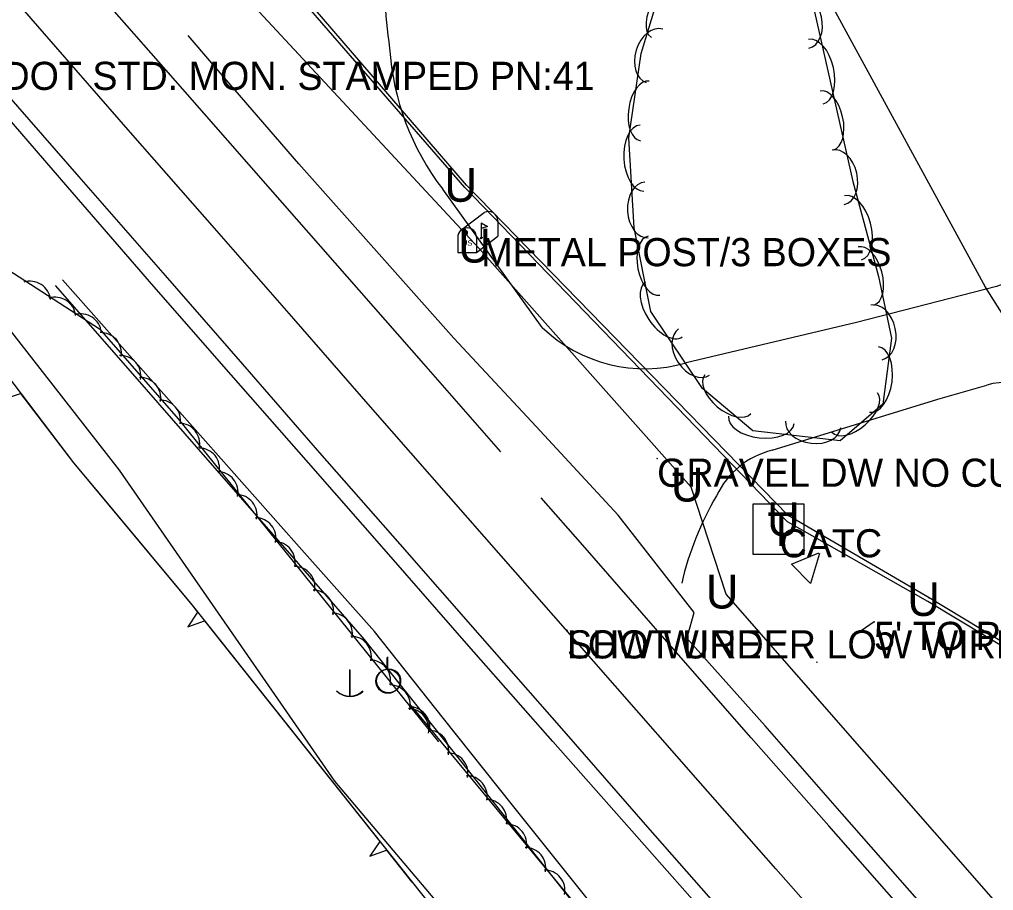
# Model space of a CAD drawing. Extents: x 954793 to 988390, y 1867850 to 1924428.
# Drawn here: x 966179.6 to 966352.5, y 1897839.5 to 1897994.2 of the extents above; entities that cross this region are included whole.
import ezdxf

# ---------------------------------------------------------------- set-up
doc = ezdxf.new("R2010")
doc.units = 0
for name, color, linetype in [('Default', 7, 'Continuous'), ('S_DITCHLINE', 7, 'Continuous'), ('S_DRIVEWAY', 7, 'Continuous'), ('S_EDGE_PAVEMENT', 7, 'Continuous'), ('S_ELECTRIC_UTILITIES_ANNOT', 7, 'Continuous'), ('S_FENCE', 7, 'Continuous'), ('S_FIBER_OPTIC_CABLE', 7, 'Continuous'), ('S_GRD_PT_SYM', 7, 'Continuous'), ('S_MAILBOX', 7, 'Continuous'), ('S_MAILBOX_ANNOT', 7, 'Continuous'), ('S_MISC_TOPO_POINT', 7, 'Continuous'), ('S_MSC_PT_SYM', 7, 'Continuous'), ('S_PAVEMENT_CROWN', 7, 'Continuous'), ('S_PRIMARY_CTL_ANNOT', 7, 'Continuous'), ('S_SHOULDER', 7, 'Continuous'), ('S_SIGN', 7, 'Continuous'), ('S_SIGN_ANNOT', 7, 'Continuous'), ('S_SURVEY_TEXT_ANNOT', 7, 'Continuous'), ('S_TELEPHONE_UTILITIES', 7, 'Continuous'), ('S_TELEPHONE_UTILITIES_ANNOT', 7, 'Continuous'), ('S_TREE', 7, 'Continuous'), ('S_UNDERGROUND_CABLE', 7, 'Continuous'), ('S_UTILITY_POLE', 7, 'Continuous'), ('S_UTL_PT_SYM', 7, 'Continuous'), ('S_WATER_UTILITIES', 7, 'Continuous')]:
    doc.layers.add(name, color=color, linetype=linetype)

msp = doc.modelspace()

# ---------------------------------------------------------------- linework, layer by layer
at = {"layer": 'S_DITCHLINE'}
for points in [[(966277.77, 1897837.5), (966265.47, 1897853.02), (966253.17, 1897868.55), (966240.87, 1897884.08), (966227.16, 1897899.8), (966213.45, 1897915.51), (966199.74, 1897931.23), (966186.02, 1897946.94)], [(966392.34, 1897728.07), (966388.47, 1897726.34), (966381.09, 1897729.16), (966372.46, 1897738.43), (966363.84, 1897747.69), (966355.22, 1897756.95), (966346.59, 1897766.21), (966332.87, 1897780.62), (966319.15, 1897795.02), (966305.43, 1897809.43), (966291.71, 1897823.83), (966279.44, 1897839.24), (966267.16, 1897854.64), (966254.89, 1897870.05), (966242.61, 1897885.46), (966228.77, 1897901.08), (966214.93, 1897916.71), (966201.08, 1897932.34), (966187.24, 1897947.96)]]:
    msp.add_lwpolyline(points, dxfattribs=at)
at = {"layer": 'S_DRIVEWAY'}
for points in [[(966298.25, 1897884.8), (966299.4, 1897888.84), (966285.91, 1897906.15), (966271.31, 1897921.87), (966256.71, 1897937.59), (966242.96, 1897953.06), (966229.22, 1897968.54), (966213.77, 1897986.42), (966209.53, 1897991.33)], [(966272.39, 1897939.5), (966254.75, 1897964.03)], [(966364.99, 1897951.02), (966353.07, 1897946.76), (966328.19, 1897940.39), (966297.97, 1897933.19), (966297.97, 1897933.19)], [(966313.22, 1897917.67), (966342.63, 1897926.74), (966351.33, 1897929.24)]]:
    msp.add_lwpolyline(points, dxfattribs=at)
for centre, major_axis, ratio, start_param, end_param in [((966324.49, 1898001.33), (7.1, -79.88), 0.998976, 4.323748, 4.776764), ((966291.37, 1897992.13), (10.81, -44.9), 0.999649, 4.541714, 5.130509), ((966290.68, 1897958.57), (17.96, 19.38), 0.99937, 3.124348, 4.168887), ((966354.85, 1897916.74), (-4.68, 12.12), 0.997266, 4.827112, 6.188789), ((966316.74, 1897903.37), (-13.94, 4.81), 0.997419, 5.284787, 6.178987), ((966349.7, 1897881.97), (-1.95, -54.11), 0.995184, 4.212702, 4.522521)]:
    msp.add_ellipse(centre, major_axis=major_axis, ratio=ratio, start_param=start_param, end_param=end_param, dxfattribs=at)
at = {"layer": 'S_EDGE_PAVEMENT'}
for points in [[(966265.05, 1897917.41), (966251.37, 1897933), (966237.77, 1897948.52), (966224.16, 1897964.05), (966208.61, 1897981.8), (966193.05, 1897999.56), (966178.87, 1898015.87), (966164.68, 1898032.17), (966151.2, 1898047.7), (966141.65, 1898058.71)], [(966305.02, 1897834.99), (966291.18, 1897850.72), (966276.29, 1897867.75), (966261.39, 1897884.77), (966247.17, 1897900.98), (966232.94, 1897917.2), (966219.25, 1897932.95), (966205.55, 1897948.71), (966190.18, 1897966.26), (966174.81, 1897983.8), (966160.53, 1898000.09), (966146.26, 1898016.39), (966132.83, 1898031.8), (966126.31, 1898039.28)], [(966556.69, 1897584.26), (966542.29, 1897600.66), (966526.72, 1897618.45), (966511.14, 1897636.23), (966496.26, 1897653.21), (966481.38, 1897670.18), (966466.51, 1897687.2), (966451.64, 1897704.23), (966438.16, 1897719.65), (966424.67, 1897735.06), (966409.56, 1897752.36), (966394.45, 1897769.66), (966380.51, 1897785.67), (966366.57, 1897801.68), (966351.81, 1897818.51), (966337.05, 1897835.34), (966323.28, 1897850.98), (966309.51, 1897866.62), (966294.55, 1897883.73), (966279.6, 1897900.83), (966272.22, 1897909.24)]]:
    msp.add_lwpolyline(points, dxfattribs=at)
at = {"layer": 'S_FENCE'}
msp.add_lwpolyline([(966321.61, 1897899.33), (966320.04, 1897893.99), (966316.69, 1897897.41), (966321.5, 1897899.48)], dxfattribs=at)
at = {"layer": 'S_FIBER_OPTIC_CABLE'}
for p, q in [((966258.99, 1897964.73), (966197.27, 1898036.41)), ((966316.08, 1897906.07), (966258.99, 1897964.73)), ((966197.33, 1897914.12), (966170.05, 1897949.09)), ((966235.58, 1897858.91), (966197.33, 1897914.12)), ((966341.1, 1897891.46), (966316.08, 1897906.07)), ((966389.25, 1897862.41), (966341.1, 1897891.46)), ((966273.18, 1897814.48), (966235.58, 1897858.91))]:
    msp.add_line(p, q, dxfattribs=at)
at = {"layer": 'S_GRD_PT_SYM'}
msp.add_lwpolyline([(966276.81, 1897885.69), (966276.81, 1897885.74), (966276.81, 1897885.69), (966276.76, 1897885.69), (966276.81, 1897885.69), (966276.81, 1897885.64), (966276.81, 1897885.69), (966276.86, 1897885.69)], dxfattribs=at)
at = {"layer": 'S_MAILBOX'}
for p, q in [((966257.96, 1897956.78), (966262.1, 1897959.89)), ((966261.58, 1897958.07), (966261.58, 1897955.36)), ((966264.53, 1897958.42), (966264.53, 1897955.7)), ((966260.73, 1897952.79), (966264.53, 1897955.7)), ((966257.41, 1897955.51), (966257.41, 1897952.79)), ((966260.73, 1897955.51), (966260.73, 1897952.79)), ((966257.41, 1897952.79), (966260.73, 1897952.79))]:
    msp.add_line(p, q, dxfattribs=at)
for points in [[(966261.58, 1897958.07), (966262.69, 1897957.41), (966261.58, 1897957.06)], [(966258.59, 1897956.62), (966258.82, 1897956.48), (966258.82, 1897956.1), (966259.12, 1897956.1), (966259.12, 1897956.46), (966258.93, 1897956.71), (966258.59, 1897956.65)]]:
    msp.add_lwpolyline(points, dxfattribs=at)
for centre, end in [((966262.87, 1897958.42), 117.5718), ((966259.07, 1897955.51), 180)]:
    msp.add_arc(centre, 1.66, 0, end, dxfattribs=at)
msp.add_ellipse((966261.58, 1897955.36), major_axis=(0.145, 0.132), ratio=0.564646, dxfattribs=at)
at = {"layer": 'S_MSC_PT_SYM'}
for points in [[(966292.81, 1897916.18), (966292.81, 1897916.23), (966292.81, 1897916.18), (966292.76, 1897916.18), (966292.81, 1897916.18), (966292.81, 1897916.13), (966292.81, 1897916.18), (966292.86, 1897916.18)], [(966331.33, 1897887.2), (966331.33, 1897887.25), (966331.33, 1897887.2), (966331.28, 1897887.2), (966331.33, 1897887.2), (966331.33, 1897887.15), (966331.33, 1897887.2), (966331.38, 1897887.2)], [(966321.19, 1897880.05), (966321.19, 1897880.1), (966321.19, 1897880.05), (966321.14, 1897880.05), (966321.19, 1897880.05), (966321.19, 1897880), (966321.19, 1897880.05), (966321.24, 1897880.05)]]:
    msp.add_lwpolyline(points, dxfattribs=at)
at = {"layer": 'S_PAVEMENT_CROWN'}
msp.add_lwpolyline([(966327.65, 1897827.67), (966313.88, 1897843.35), (966300.1, 1897859.03), (966285.36, 1897875.84), (966270.62, 1897892.65), (966256.27, 1897909.02), (966241.93, 1897925.38), (966228.28, 1897941.01), (966214.62, 1897956.65), (966199.33, 1897974.13), (966184.03, 1897991.61), (966169.77, 1898008.02)], dxfattribs=at)
at = {"layer": 'S_SHOULDER'}
for points in [[(966303.14, 1897833.34), (966289.22, 1897849.08), (966274.31, 1897865.97), (966259.39, 1897882.86), (966245.17, 1897899.15), (966230.94, 1897915.43), (966217.21, 1897931.09), (966203.47, 1897946.76), (966188.18, 1897964.39), (966172.89, 1897982.03), (966158.65, 1897998.25), (966144.41, 1898014.47), (966130.85, 1898029.95), (966122.89, 1898039.03)], [(966558.56, 1897586.04), (966544.15, 1897602.56), (966528.65, 1897620.34), (966513.15, 1897638.13), (966498.37, 1897655.11), (966483.59, 1897672.1), (966468.73, 1897689.17), (966453.87, 1897706.23), (966440.45, 1897721.69), (966427.03, 1897737.14), (966412.09, 1897754.39), (966397.14, 1897771.65), (966382.99, 1897787.71), (966368.83, 1897803.77), (966354.11, 1897820.62), (966339.38, 1897837.46), (966325.68, 1897853.09), (966311.99, 1897868.71), (966298.11, 1897884.29)]]:
    msp.add_lwpolyline(points, dxfattribs=at)
at = {"layer": 'S_SIGN'}
msp.add_line((966331.33, 1897887.2), (966328.26, 1897885.04), dxfattribs=at)
at = {"layer": 'S_TELEPHONE_UTILITIES'}
msp.add_lwpolyline([(966309.84, 1897899.14), (966309.84, 1897908.14), (966318.84, 1897908.14), (966318.84, 1897899.14)], close=True, dxfattribs=at)
at = {"layer": 'S_TREE'}
for p, q in [((966176.8, 1897926.77), (966179.81, 1897927.77)), ((966211.23, 1897888.89), (966209.47, 1897886.28)), ((966209.47, 1897886.28), (966212.45, 1897887.35)), ((966243.55, 1897848.19), (966241.79, 1897845.59)), ((966241.79, 1897845.59), (966244.77, 1897846.65))]:
    msp.add_line(p, q, dxfattribs=at)
for points in [[(966004.3, 1897880.13), (966059.66, 1897915.24), (966086.88, 1897921.09), (966104.68, 1897925.07), (966112.45, 1897935.52), (966106.92, 1897948.08), (966090.61, 1897968.77), (966074.51, 1897985.5), (966067.36, 1897991.4), (966058.74, 1898002.25), (966054.98, 1898014.16), (966059.62, 1898020.14), (966075.09, 1898023.53), (966101.4, 1898008.02), (966123.07, 1897993.04), (966147.23, 1897971.38), (966166.44, 1897945.33), (966189.19, 1897915.45), (966210.24, 1897890.13), (966252.56, 1897836.85)], [(966319.9, 1897999.25), (966327.57, 1897965.38), (966332.11, 1897948.56), (966334.43, 1897937.57), (966332.87, 1897925.87), (966325.28, 1897919.34), (966309.79, 1897921.12), (966300.85, 1897928.63), (966291.69, 1897942.34), (966288.74, 1897957.16), (966287.77, 1897973.15), (966289.98, 1897988.15), (966292.25, 1897995.52), (966294.55, 1897998.96), (966306.08, 1898004.97), (966313.11, 1898004.57), (966318.51, 1898000.87), (966320.58, 1897997.56)], [(966148.95, 1897968.26), (966193.8, 1897939.26), (966207.79, 1897923.25), (966253.99, 1897865.87)], [(966179.81, 1897927.77), (966189.19, 1897915.45), (966195.27, 1897908.13)], [(966195.27, 1897908.13), (966210.24, 1897890.13), (966211.23, 1897888.89)], [(966212.45, 1897887.35), (966228, 1897867.77)], [(966249.08, 1897872.34), (966354.07, 1897745.39), (966390.72, 1897702.43), (966457.35, 1897631.88), (966516.54, 1897569.35)], [(966228, 1897867.77), (966243.55, 1897848.19)], [(966244.77, 1897846.65), (966249.28, 1897840.97)]]:
    msp.add_lwpolyline(points, dxfattribs=at)
for centre, start, end in [((966181.48, 1897944.06), 6.3158, 107.9127), ((966185.95, 1897941.21), 6.3158, 107.9127), ((966190.52, 1897938.25), 6.3158, 107.9127), ((966194.06, 1897934.92), 350.3475, 91.9444), ((966197.51, 1897930.86), 350.3475, 91.9444), ((966201.05, 1897926.93), 350.3475, 91.9444), ((966204.56, 1897922.95), 350.3475, 91.9444), ((966207.96, 1897918.84), 348.0399, 89.6368), ((966211.48, 1897914.43), 348.0399, 89.6368), ((966214.77, 1897910.22), 348.0399, 89.6368), ((966218.14, 1897906.16), 348.0399, 89.6368), ((966221.49, 1897902.05), 348.0399, 89.6368), ((966224.9, 1897897.81), 348.0399, 89.6368), ((966228.42, 1897893.39), 348.0399, 89.6368), ((966231.71, 1897889.19), 348.0399, 89.6368), ((966235.08, 1897885.12), 348.0399, 89.6368), ((966238.43, 1897881.01), 348.0399, 89.6368), ((966241.84, 1897876.77), 348.0399, 89.6368), ((966245.36, 1897872.35), 348.0399, 89.6368), ((966248.64, 1897868.15), 348.0399, 89.6368), ((966248.83, 1897868.46), 348.7944, 90.3913), ((966252.17, 1897864.31), 348.7944, 90.3913), ((966255.59, 1897860.28), 348.7944, 90.3913), ((966259, 1897856.22), 348.7944, 90.3913), ((966262.47, 1897852.02), 348.7944, 90.3913), ((966266.04, 1897847.65), 348.7944, 90.3913), ((966269.39, 1897843.49), 348.7944, 90.3913), ((966272.81, 1897839.47), 348.7944, 90.3913)]:
    msp.add_arc(centre, 3.64, start, end, dxfattribs=at)
for centre, major_axis, ratio in [((966295.04, 1897995.87), (-3.26, -4.88), 0.55008), ((966318.67, 1897993.89), (-1.09, 4.83), 0.685311), ((966292.34, 1897987.73), (-1.46, -4.74), 0.685311), ((966320.97, 1897984.92), (-1.29, 5.72), 0.55008), ((966290.62, 1897977.94), (-0.78, -5.29), 0.540699), ((966322.93, 1897976.27), (-1.18, 5.21), 0.540699), ((966290.12, 1897969.57), (0.35, -5.86), 0.55008), ((966324.95, 1897966.16), (-1.09, 4.83), 0.685311), ((966290.94, 1897960.34), (0.3, -4.95), 0.685311), ((966327.58, 1897957.18), (-1.53, 5.67), 0.55008), ((966292.24, 1897950.45), (1.04, -5.24), 0.540699), ((966329.9, 1897948.62), (-1.39, 5.16), 0.540699), ((966294.02, 1897942.67), (3.26, -4.88), 0.55008), ((966331.77, 1897938.61), (-1.02, 4.85), 0.685311), ((966299.38, 1897935.12), (2.75, -4.12), 0.685311), ((966331.31, 1897930.23), (0.78, 5.82), 0.55008), ((966305.35, 1897927.62), (4.09, -3.44), 0.540699), ((966327.87, 1897924.38), (4.05, 3.49), 0.540699), ((966311.31, 1897923.08), (5.83, -0.67), 0.55008), ((966320.53, 1897922.28), (4.92, -0.57), 0.685311)]:
    msp.add_ellipse(centre, major_axis=major_axis, ratio=ratio, start_param=3.141593, end_param=6.283185, dxfattribs=at)
at = {"layer": 'S_UNDERGROUND_CABLE'}
for p, q in [((966261.13, 1897953.54), (966185.07, 1898035.55)), ((966258.67, 1897964.36), (966196.56, 1898036)), ((966315.95, 1897904.98), (966258.67, 1897964.36)), ((966298.88, 1897911.11), (966261.13, 1897953.54)), ((966305.08, 1897892.1), (966298.88, 1897911.11)), ((966340.86, 1897890.78), (966315.95, 1897904.98)), ((966362.5, 1897826.48), (966305.08, 1897892.1)), ((966388.86, 1897861.94), (966340.86, 1897890.78))]:
    msp.add_line(p, q, dxfattribs=at)
at = {"layer": 'S_UTILITY_POLE'}
for p, q in [((966244.9, 1897878.78), (966244.9, 1897880.88)), ((966245.02, 1897878.87), (966245.02, 1897880.98)), ((966238.17, 1897878.72), (966238.17, 1897874)), ((966238.23, 1897878.64), (966238.23, 1897873.91))]:
    msp.add_line(p, q, dxfattribs=at)
for centre in [(966245.02, 1897876.63), (966245.14, 1897876.73)]:
    msp.add_circle(centre, 2.13, dxfattribs=at)
for centre in [(966238.23, 1897877.42), (966238.29, 1897877.34)]:
    msp.add_arc(centre, 3.41, 226.3972, 313.6028, dxfattribs=at)
at = {"layer": 'S_UTL_PT_SYM'}
for points in [[(966258.99, 1897964.73), (966258.99, 1897964.78), (966258.99, 1897964.73), (966258.94, 1897964.73), (966258.99, 1897964.73), (966258.99, 1897964.68), (966258.99, 1897964.73), (966259.04, 1897964.73)], [(966351.09, 1897946.65), (966351.09, 1897946.7), (966351.09, 1897946.65), (966351.04, 1897946.65), (966351.09, 1897946.65), (966351.09, 1897946.6), (966351.09, 1897946.65), (966351.14, 1897946.65)], [(966197.33, 1897914.12), (966197.33, 1897914.17), (966197.33, 1897914.12), (966197.28, 1897914.12), (966197.33, 1897914.12), (966197.33, 1897914.07), (966197.33, 1897914.12), (966197.38, 1897914.12)], [(966316.08, 1897906.07), (966316.08, 1897906.12), (966316.08, 1897906.07), (966316.03, 1897906.07), (966316.08, 1897906.07), (966316.08, 1897906.02), (966316.08, 1897906.07), (966316.13, 1897906.07)], [(966341.1, 1897891.46), (966341.1, 1897891.51), (966341.1, 1897891.46), (966341.05, 1897891.46), (966341.1, 1897891.46), (966341.1, 1897891.41), (966341.1, 1897891.46), (966341.15, 1897891.46)], [(966276.81, 1897885.69), (966276.81, 1897885.74), (966276.81, 1897885.69), (966276.76, 1897885.69), (966276.81, 1897885.69), (966276.81, 1897885.64), (966276.81, 1897885.69), (966276.86, 1897885.69)], [(966235.58, 1897858.91), (966235.58, 1897858.96), (966235.58, 1897858.91), (966235.53, 1897858.91), (966235.58, 1897858.91), (966235.58, 1897858.86), (966235.58, 1897858.91), (966235.63, 1897858.91)]]:
    msp.add_lwpolyline(points, dxfattribs=at)
at = {"layer": 'S_WATER_UTILITIES'}
for p, q in [((966351.09, 1897946.65), (966312.55, 1898017.63)), ((966368.94, 1897918.36), (966351.09, 1897946.65))]:
    msp.add_line(p, q, dxfattribs=at)

# ---------------------------------------------------------------- texts
at = {"layer": 'Default'}
for p in [(966255.04, 1897961.81), (966257.5, 1897951), (966295.25, 1897908.56), (966312.32, 1897902.43), (966301.45, 1897889.56), (966337.23, 1897888.24)]:
    msp.add_text('U', height=6, rotation=360, dxfattribs=at).set_placement(p)
at = {"layer": 'S_ELECTRIC_UTILITIES_ANNOT'}
msp.add_text('LOW WIRE', height=5, dxfattribs=at).set_placement((966276.81, 1897880.69))
at = {"layer": 'S_MAILBOX'}
msp.add_text('US', height=0.96, rotation=360, dxfattribs=at).set_placement((966258.17, 1897953.99))
at = {"layer": 'S_MAILBOX_ANNOT'}
msp.add_text('METAL POST/3 BOXES', height=5, dxfattribs=at).set_placement((966261.58, 1897950.36))
at = {"layer": 'S_MISC_TOPO_POINT'}
msp.add_text('SHOT UNDER LOW WIRE', height=5, dxfattribs=at).set_placement((966276.81, 1897880.69))
at = {"layer": 'S_PRIMARY_CTL_ANNOT'}
msp.add_text('PD:ARDOT STD. MON. STAMPED PN:41', height=5, dxfattribs=at).set_placement((966156.14, 1897981.67))
at = {"layer": 'S_SIGN_ANNOT'}
msp.add_text("5' TO POST TY:M NONE NONE", height=5, dxfattribs=at).set_placement((966331.33, 1897882.2))
at = {"layer": 'S_SURVEY_TEXT_ANNOT'}
msp.add_text('GRAVEL DW NO CUS', height=5, dxfattribs=at).set_placement((966292.81, 1897911.18))
at = {"layer": 'S_TELEPHONE_UTILITIES'}
msp.add_text('T', height=6, rotation=360, dxfattribs=at).set_placement((966312.4, 1897900.64))
at = {"layer": 'S_TELEPHONE_UTILITIES_ANNOT'}
msp.add_text('CATC', height=5, dxfattribs=at).set_placement((966314.56, 1897898.65))

doc.saveas('drawing.dxf')
